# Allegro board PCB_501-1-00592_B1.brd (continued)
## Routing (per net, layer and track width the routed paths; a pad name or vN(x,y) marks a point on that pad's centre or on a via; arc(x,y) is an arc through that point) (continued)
PCIE_NVM_RX2_N: length 48.8
  TOP w0.114: J7.17 20.59,24.72 20.5,24.82 18.06,24.82 17.91,24.67 17.91,24.42 18.02,24.3 19.03,24.3 19.25,24.08 19.25,23.53 18.96,23.23 18.02,23.23 17.91,23.12 17.91,22.89 18.02,22.78 19.03,22.78 19.25,22.55 19.25,22.02 18.95,21.71 18.02,21.71 17.91,21.6 17.91,21.37 18.02,21.25 19.03,21.25 19.25,21.03 19.25,20.48 18.96,20.19 18.02,20.19 17.91,20.07 17.91,19.8 18.02,19.69 19.08,19.69 19.3,19.46 19.3,18.92 19.01,18.62 18.02,18.62 17.91,18.51 17.91,18.28 18.02,18.17 19.08,18.17 19.3,17.94 19.3,17.39 19.01,17.1 18.02,17.1 17.91,16.98 17.91,16.76 18.02,16.64 19.08,16.64 19.3,16.42 19.3,15.87 19.01,15.58 18.02,15.58 17.91,15.46 17.91,15.22 18.02,15.11 19.04,15.11 19.33,14.81 19.33,14.4 18.97,14.04 11.87,14.04 11.05,14.86 11.05,22.91 9.64,24.31 8.81,24.31 R6.1
PCIE_NVM_RX2_P: length 49.4
  TOP w0.114: R1.1 8.77,24.62 9.77,24.62 9.99,24.4 10.16,24.4 10.22,24.46 10.38,24.46 10.55,24.3 10.55,24.14 10.48,24.07 10.48,23.91 10.64,23.75 10.8,23.75 10.87,23.82 11.03,23.82 11.19,23.66 11.19,23.49 11.13,23.43 11.13,23.27 11.35,23.04 11.35,14.99 11.99,14.35 18.85,14.35 19.02,14.52 19.02,14.69 18.91,14.8 17.9,14.8 17.6,15.09 17.6,15.59 17.9,15.88 18.88,15.88 19,15.99 19,16.22 18.88,16.34 17.9,16.34 17.6,16.63 17.6,17.11 17.9,17.4 18.88,17.4 19,17.52 19,17.75 18.88,17.86 17.9,17.86 17.6,18.15 17.6,18.64 17.9,18.93 18.88,18.93 19,19.04 19,19.27 18.88,19.39 17.9,19.39 17.6,19.68 17.6,20.2 17.9,20.49 18.83,20.49 18.95,20.61 18.95,20.83 18.83,20.95 17.9,20.95 17.6,21.24 17.6,21.72 17.9,22.02 18.82,22.02 18.95,22.14 18.95,22.36 18.83,22.47 17.9,22.47 17.6,22.77 17.6,23.25 17.9,23.54 18.83,23.54 18.95,23.65 18.95,23.88 18.83,24 17.9,24 17.6,24.29 17.6,24.79 17.93,25.12 20.37,25.12 20.47,25.22 J7.19
PCIE_NVM_RX3_N: length 44.3
  TOP w0.114: J7.5 21.82,21.72 21.92,21.82 22.81,21.82 23.03,21.6 23.03,21.44 22.9,21.31 22.9,21.15 23.06,20.99 23.22,20.99 23.35,21.12 23.51,21.12 23.83,20.8 23.83,18.27 23.69,18.13 22.31,18.13 22.02,17.83 22.02,17.35 22.31,17.06 23.71,17.06 23.83,16.95 23.83,16.74 23.69,16.6 22.31,16.6 22.02,16.31 22.02,15.83 22.31,15.54 23.71,15.54 23.83,15.42 23.83,15.22 23.69,15.08 22.31,15.08 22.02,14.79 22.02,14.3 22.31,14.01 23.71,14.01 23.83,13.9 23.83,13.41 23.7,13.28 10.79,13.28 9.93,14.15 9.93,21.72 9.35,22.3 8.81,22.3 R8.1
PCIE_NVM_RX3_P: length 44.8
  TOP w0.114: R7.1 8.78,22 9.22,22 9.63,21.59 9.63,14.02 10.67,12.98 23.83,12.98 24.13,13.28 24.13,14.02 23.84,14.32 22.44,14.32 22.33,14.43 22.33,14.66 22.44,14.77 23.81,14.77 24.13,15.09 24.13,15.57 23.86,15.84 22.44,15.84 22.33,15.96 22.33,16.18 22.44,16.3 23.81,16.3 24.13,16.62 24.13,17.1 23.86,17.36 22.44,17.36 22.33,17.48 22.33,17.71 22.44,17.82 23.81,17.82 24.13,18.14 24.13,20.93 22.93,22.12 21.87,22.12 21.77,22.22 J7.7
PCIE_NVM_RX4_N: length 38.8
  TOP w0.114: J8.41 20.51,68.95 20.41,69.05 19.92,69.05 18.72,67.85 18.72,67.69 18.84,67.57 18.84,67.41 18.68,67.25 18.52,67.25 18.4,67.36 18.24,67.36 13.56,62.69 13.56,42.19 10.22,38.84 10.22,38.68 10.3,38.6 10.3,38.44 10.14,38.28 9.98,38.28 9.9,38.36 9.73,38.36 9.39,38.01 8.85,38.01 8.43,37.59 R10.1
PCIE_NVM_RX4_P: length 37.8
  TOP w0.114: R9.1 8.43,38.74 8.85,38.32 9.26,38.32 13.26,42.32 13.26,62.81 19.8,69.35 20.43,69.35 20.53,69.45 J8.43
PCIE_NVM_RX5_N: length 42.8
  TOP w0.114: J8.29 21.02,66.07 18.82,66.07 18.3,65.54 18.3,65.38 18.4,65.27 18.4,65.11 18.24,64.95 18.08,64.95 17.97,65.06 17.81,65.06 17.65,64.89 17.65,64.73 17.75,64.63 17.75,64.47 17.59,64.3 17.43,64.3 17.33,64.41 17.16,64.41 14.63,61.87 14.63,40.39 13.89,39.64 13.47,39.64 12.94,40.18 12.77,40.18 12.61,40.02 12.61,39.86 13.15,39.32 13.15,38.91 12.81,38.57 12.39,38.57 11.86,39.1 11.7,39.1 11.53,38.94 11.53,38.78 12.07,38.24 12.07,37.83 10.03,35.79 8.86,35.79 R12.1
PCIE_NVM_RX5_P: length 41.8
  TOP w0.114: R11.1 8.73,36.09 9.91,36.09 11.77,37.95 11.77,38.11 11.23,38.65 11.23,39.07 11.57,39.41 11.98,39.41 12.52,38.87 12.68,38.87 12.84,39.03 12.84,39.19 12.31,39.73 12.31,40.15 12.65,40.49 13.06,40.49 13.6,39.95 13.76,39.95 14.33,40.51 14.33,62 18.69,66.37 21.04,66.37 21.12,66.45 J8.31
PCIE_NVM_RX6_N: length 46
  TOP w0.114: R14.1 8.79,33.44 9.54,33.44 15.65,39.55 15.65,50.29 15.76,50.41 16.47,50.41 16.76,50.7 16.76,51.18 16.47,51.48 15.76,51.48 15.65,51.59 15.65,51.82 15.76,51.93 16.47,51.93 16.76,52.23 16.76,52.71 16.47,53 15.76,53 15.65,53.11 15.65,53.34 15.76,53.46 16.47,53.46 16.76,53.75 16.76,54.23 16.47,54.52 15.76,54.52 15.65,54.64 15.65,54.87 15.76,54.98 16.47,54.98 16.76,55.27 16.76,55.76 16.47,56.05 15.76,56.05 15.65,56.16 15.65,61.39 17.3,63.04 18.26,63.04 18.38,62.93 18.38,62.8 18.49,62.69 18.72,62.69 18.83,62.8 18.83,62.93 18.95,63.04 19.18,63.04 19.29,62.93 19.29,62.8 19.41,62.69 19.63,62.69 19.75,62.8 19.75,62.93 19.86,63.04 21.05,63.04 J8.17
PCIE_NVM_RX6_P: length 45.1
  TOP w0.114: J8.19 21.04,63.35 17.17,63.35 15.34,61.52 15.34,56.04 15.63,55.74 16.34,55.74 16.46,55.63 16.46,55.4 16.34,55.29 15.63,55.29 15.34,54.99 15.34,54.51 15.63,54.22 16.34,54.22 16.46,54.1 16.46,53.88 16.34,53.76 15.63,53.76 15.34,53.47 15.34,52.99 15.63,52.69 16.34,52.69 16.46,52.58 16.46,52.35 16.34,52.24 15.63,52.24 15.34,51.95 15.34,51.46 15.63,51.17 16.34,51.17 16.46,51.06 16.46,50.83 16.34,50.71 15.63,50.71 15.34,50.42 15.34,39.67 9.41,33.74 8.79,33.74 R13.1
PCIE_NVM_RX7_N: length 48.5
  TOP w0.114: J8.5 20.47,59.95 20.37,60.05 19.43,60.05 18.16,61.32 17.2,61.32 16.59,60.71 16.59,60.08 16.74,59.92 16.74,59.47 16.59,59.31 16.59,58.86 16.74,58.7 16.74,58.25 16.59,58.09 16.59,57.23 17.6,56.21 17.6,49.55 17.31,49.26 16.68,49.26 16.56,49.15 16.56,48.92 16.68,48.8 17.31,48.8 17.6,48.51 17.6,48.03 17.31,47.74 16.68,47.74 16.56,47.62 16.56,47.39 16.68,47.28 17.31,47.28 17.6,46.99 17.6,46.51 17.31,46.21 16.68,46.21 16.56,46.1 16.56,45.87 16.68,45.76 17.31,45.76 17.6,45.46 17.6,44.98 17.31,44.69 16.68,44.69 16.56,44.57 16.56,44.35 16.68,44.23 17.31,44.23 17.6,43.94 17.6,43.46 17.31,43.17 16.68,43.17 16.56,43.05 16.56,42.82 16.68,42.71 17.31,42.71 17.6,42.42 17.6,38.91 9.84,31.15 8.79,31.15 R16.1
PCIE_NVM_RX7_P: length 48.2
  TOP w0.114: R15.1 8.41,31.88 8.83,31.46 9.72,31.46 17.3,39.04 17.3,42.29 17.18,42.4 16.55,42.4 16.26,42.7 16.26,43.18 16.55,43.47 17.18,43.47 17.3,43.58 17.3,43.81 17.18,43.93 16.55,43.93 16.26,44.22 16.26,44.7 16.55,44.99 17.18,44.99 17.3,45.11 17.3,45.34 17.18,45.45 16.55,45.45 16.26,45.74 16.26,46.23 16.55,46.52 17.18,46.52 17.3,46.63 17.3,46.86 17.18,46.98 16.55,46.98 16.26,47.27 16.26,47.75 16.55,48.04 17.18,48.04 17.3,48.16 17.3,48.38 17.18,48.5 16.55,48.5 16.26,48.79 16.26,49.27 16.55,49.57 17.18,49.57 17.3,49.68 17.3,56.08 16.28,57.1 16.28,60.83 17.07,61.62 18.29,61.62 19.56,60.35 20.37,60.35 20.47,60.45 J8.7
PCIE_NVM_TX0_N: length 50.1
  TOP w0.114: v2(22.26,32.21) 22.15,32.32 21.83,32.32 21.73,32.22 J7.47
  BOTTOM w0.114: v2(22.26,32.21) 22.39,32.33 23.88,32.33 24.21,32 24.21,31.7 24.09,31.59 23.94,31.59 23.83,31.47 23.83,31.25 23.94,31.13 24.07,31.13 24.21,30.99 24.21,30.79 24.09,30.67 23.94,30.67 23.83,30.56 23.83,30.33 23.94,30.22 24.07,30.22 24.21,30.08 24.21,8.59 23.67,8.05 17.91,8.05 17.32,8.64 17.32,21.89 16.9,22.31 16.28,22.31 R79.2
PCIE_NVM_TX0_P: length 50.2
  TOP w0.114: J7.49 21.76,32.72 21.86,32.62 22.15,32.62 v2(22.26,32.74)
  BOTTOM w0.114: v2(22.26,32.74) 22.36,32.64 24,32.64 24.51,32.13 24.51,8.46 23.8,7.75 17.78,7.75 17.02,8.51 17.02,21.77 16.78,22.01 16.29,22.01 R78.2
PCIE_NVM_TX1_N: length 53.4
  TOP w0.114: J7.35 21.75,29.22 21.85,29.32 22.61,29.32 v2(22.72,29.21)
  BOTTOM w0.114: v2(22.72,29.21) 22.83,29.31 23.09,29.31 23.32,29.08 23.32,18.43 23.2,18.32 23.05,18.32 22.94,18.2 22.94,17.98 23.05,17.86 23.2,17.86 23.32,17.75 23.32,17.52 23.2,17.4 23.05,17.4 22.94,17.29 22.94,17.06 23.05,16.95 23.2,16.95 23.32,16.83 23.32,15.39 23.2,15.28 22.72,15.28 22.43,14.98 22.43,14.5 22.72,14.21 23.2,14.21 23.32,14.1 23.32,13.87 23.2,13.75 22.72,13.75 22.43,13.46 22.43,12.98 22.72,12.69 23.2,12.69 23.32,12.57 23.32,12.34 23.2,12.23 22.72,12.23 22.43,11.94 22.43,11.46 22.72,11.16 23.2,11.16 23.32,11.05 23.32,10.82 23.2,10.71 22.72,10.71 22.43,10.41 22.43,9.93 22.72,9.64 23.18,9.64 23.32,9.5 23.32,9.3 23.17,9.14 18.67,9.14 18.49,9.32 18.49,22.91 17.56,23.84 12.98,23.84 R81.2
PCIE_NVM_TX1_P: length 53.4
  TOP w0.114: J7.37 21.76,29.72 21.86,29.62 22.61,29.62 v2(22.72,29.74)
  BOTTOM w0.114: R80.2 12.98,23.53 17.44,23.53 18.19,22.78 18.19,9.19 18.54,8.84 23.29,8.84 23.62,9.17 23.62,9.63 23.3,9.94 22.85,9.94 22.73,10.06 22.73,10.29 22.85,10.4 23.33,10.4 23.62,10.69 23.62,11.17 23.33,11.47 22.85,11.47 22.73,11.58 22.73,11.81 22.85,11.92 23.33,11.92 23.62,12.22 23.62,12.7 23.33,12.99 22.85,12.99 22.73,13.11 22.73,13.33 22.85,13.45 23.33,13.45 23.62,13.74 23.62,14.22 23.33,14.52 22.85,14.52 22.73,14.63 22.73,14.86 22.85,14.97 23.33,14.97 23.62,15.27 23.62,29.21 23.22,29.62 22.84,29.62 v2(22.72,29.74)
PCIE_NVM_TX2_N: length 50.1
  TOP w0.114: v2(16.6,25.36) 16.6,25.21 16.41,25.02 16.41,24.77 16.29,24.65 16.09,24.65 15.98,24.54 15.98,24.31 16.09,24.2 16.29,24.2 16.41,24.08 16.41,23.24 16.29,23.13 14.95,23.13 14.66,22.83 14.66,22.35 14.95,22.06 16.29,22.06 16.41,21.95 16.41,21.72 16.29,21.6 14.95,21.6 14.66,21.31 14.66,20.83 14.95,20.54 16.29,20.54 16.41,20.42 16.41,20.19 16.29,20.08 14.95,20.08 14.66,19.79 14.66,19.3 14.95,19.01 16.29,19.01 16.41,18.9 16.41,18.67 16.29,18.55 14.95,18.55 14.66,18.26 14.66,17.78 14.95,17.49 16.29,17.49 16.41,17.37 16.41,17.14 16.29,17.03 14.95,17.03 14.66,16.74 14.66,16.26 14.95,15.96 16.29,15.96 16.41,15.85 16.41,15.52 16.23,15.34 13.31,15.34 12.57,16.08 12.57,25.25 13.64,26.32 17.53,26.32 17.65,26.21 17.65,26.02 17.76,25.91 17.99,25.91 18.1,26.02 18.1,26.21 18.22,26.32 18.45,26.32 18.56,26.21 18.56,26.02 18.67,25.91 18.9,25.91 19.02,26.02 19.02,26.21 19.13,26.32 20.39,26.32 20.49,26.22 J7.23
  BOTTOM w0.114: v2(16.6,25.36) 16.28,25.36 R83.2
PCIE_NVM_TX2_P: length 50.2
  TOP w0.114: J7.25 20.55,26.72 20.45,26.62 13.52,26.62 12.27,25.37 12.27,15.95 13.18,15.04 16.36,15.04 16.71,15.39 16.71,15.98 16.42,16.27 15.07,16.27 14.96,16.38 14.96,16.61 15.07,16.73 16.42,16.73 16.71,17.02 16.71,17.5 16.42,17.79 15.07,17.79 14.96,17.91 14.96,18.14 15.07,18.25 16.42,18.25 16.71,18.54 16.71,19.02 16.42,19.32 15.07,19.32 14.96,19.43 14.96,19.66 15.07,19.77 16.42,19.77 16.71,20.07 16.71,20.55 16.42,20.84 15.07,20.84 14.96,20.95 14.96,21.18 15.07,21.3 16.42,21.3 16.71,21.59 16.71,22.07 16.42,22.36 15.07,22.36 14.96,22.48 14.96,22.71 15.07,22.82 16.42,22.82 16.71,23.11 16.71,24.89 16.88,25.06 v2(17.04,25.06)
  BOTTOM w0.114: R82.2 16.18,24.95 16.94,24.95 v2(17.04,25.06)
PCIE_NVM_TX3_N: length 53.5
  TOP w0.114: J7.11 21.05,23.32 20.15,23.32 v2(20.04,23.21)
  BOTTOM w0.114: R85.2 12.98,26.89 20.92,26.89 21.39,26.42 21.39,25.07 21.01,24.69 19.68,24.69 19.33,24.33 19.33,17.79 19.47,17.65 20.05,17.65 20.35,17.35 20.35,16.87 20.05,16.58 19.44,16.58 19.33,16.47 19.33,16.26 19.47,16.12 20.05,16.12 20.35,15.83 20.35,15.35 20.05,15.06 19.44,15.06 19.33,14.94 19.33,14.74 19.47,14.6 20.05,14.6 20.35,14.31 20.35,13.82 20.05,13.53 19.44,13.53 19.33,13.42 19.33,13.21 19.47,13.08 20.05,13.08 20.35,12.78 20.35,12.3 20.05,12.01 19.44,12.01 19.33,11.89 19.33,11.69 19.47,11.55 20.05,11.55 20.35,11.26 20.35,10.78 20.05,10.48 19.42,10.48 19.3,10.37 19.3,10.13 19.46,9.98 21.18,9.98 21.39,10.19 21.39,20.62 21.27,20.73 21.09,20.73 20.98,20.84 20.98,21.07 21.09,21.19 21.27,21.19 21.39,21.3 21.39,21.53 21.27,21.64 21.09,21.64 20.98,21.76 20.98,21.99 21.09,22.1 21.27,22.1 21.39,22.22 21.39,22.66 20.73,23.32 20.15,23.32 v2(20.04,23.21)
PCIE_NVM_TX3_P: length 53.4
  TOP w0.114: v2(20.04,23.74) 20.15,23.62 21.04,23.62 J7.13
  BOTTOM w0.114: R84.2 12.98,26.58 20.79,26.58 21.08,26.29 21.08,25.2 20.88,24.99 19.56,24.99 19.02,24.46 19.02,17.66 19.34,17.34 19.93,17.34 20.04,17.23 20.04,17 19.93,16.89 19.32,16.89 19.02,16.59 19.02,16.14 19.34,15.82 19.93,15.82 20.04,15.7 20.04,15.48 19.93,15.36 19.32,15.36 19.02,15.07 19.02,14.61 19.34,14.29 19.93,14.29 20.04,14.18 20.04,13.95 19.93,13.84 19.32,13.84 19.02,13.54 19.02,13.09 19.34,12.77 19.93,12.77 20.04,12.66 20.04,12.43 19.93,12.31 19.32,12.31 19.02,12.02 19.02,11.56 19.34,11.25 19.93,11.25 20.04,11.13 20.04,10.9 19.93,10.79 19.29,10.79 19,10.5 19,10.01 19.33,9.68 21.31,9.68 21.69,10.06 21.69,22.78 20.85,23.62 20.15,23.62 v2(20.04,23.74)
PCIE_NVM_TX4_N: length 50.6
  TOP w0.114: v2(20.04,70.43) 20.09,70.43 20.21,70.55 20.4,70.55 20.51,70.45 J8.47
  BOTTOM w0.114: v2(20.04,70.43) 20.09,70.43 20.19,70.54 22.5,70.54 23.24,69.8 23.24,69.5 23.13,69.38 23.03,69.38 22.91,69.27 22.91,69.04 23.03,68.93 23.13,68.93 23.24,68.81 23.24,68.13 23.13,68.02 22.97,68.02 22.86,67.9 22.86,67.67 22.97,67.56 23.13,67.56 23.24,67.44 23.24,51.84 19,47.6 19,30.96 16.45,28.41 16.29,28.41 R87.2
PCIE_NVM_TX4_P: length 50.7
  TOP w0.114: v2(20.04,70.97) 20.09,70.97 20.2,70.86 20.39,70.86 20.48,70.95 J8.49
  BOTTOM w0.114: R86.2 16.29,28.11 16.57,28.11 19.3,30.84 19.3,47.47 23.55,51.71 23.55,69.93 22.63,70.84 20.22,70.84 20.09,70.97 v2(20.04,70.97)
PCIE_NVM_TX5_N: length 53.4
  TOP w0.114: J8.35 20.46,67.45 20.36,67.55 19.79,67.55 v2(19.67,67.43)
  BOTTOM w0.114: v2(19.67,67.43) 19.8,67.56 20.63,67.56 21.54,66.65 21.54,57.79 21.42,57.68 21.3,57.68 21.18,57.56 21.18,57.33 21.3,57.22 21.42,57.22 21.54,57.1 21.54,56.87 21.42,56.76 21.3,56.76 21.18,56.65 21.18,56.42 21.3,56.3 21.42,56.3 21.54,56.19 21.54,55.73 21.24,55.42 20.23,55.42 19.94,55.13 19.94,54.65 20.23,54.36 21.37,54.36 21.49,54.24 21.49,54.04 21.35,53.9 20.23,53.9 19.94,53.61 19.94,53.13 20.23,52.83 21.37,52.83 21.49,52.72 21.49,52.46 21.35,52.32 20.37,52.32 19.74,51.69 19.74,50.19 17.83,48.29 17.83,31.17 16.6,29.93 12.98,29.93 R89.2
PCIE_NVM_TX5_P: length 53.5
  TOP w0.114: v2(19.67,67.97) 19.79,67.85 20.38,67.85 20.47,67.95 J8.37
  BOTTOM w0.114: v2(19.67,67.97) 19.77,67.87 20.75,67.87 21.84,66.78 21.84,55.6 21.36,55.12 20.36,55.12 20.24,55 20.24,54.78 20.36,54.66 21.5,54.66 21.79,54.37 21.79,53.91 21.48,53.6 20.36,53.6 20.24,53.48 20.24,53.28 20.36,53.16 21.5,53.16 21.79,52.87 21.79,52.34 21.48,52.02 20.5,52.02 20.04,51.56 20.04,50.06 18.14,48.16 18.14,31.04 16.73,29.63 12.98,29.63 R88.2
PCIE_NVM_TX6_N: length 50.1
  TOP w0.114: J8.23 20.49,64.45 20.39,64.55 20.1,64.55 v2(19.99,64.43)
  BOTTOM w0.114: R91.2 16.29,31.46 16.65,31.46 16.87,31.67 16.87,50.53 17.16,50.82 18.3,50.82 18.41,50.94 18.41,51.17 18.3,51.28 17.16,51.28 16.87,51.57 16.87,52.06 17.16,52.35 18.3,52.35 18.41,52.46 18.41,52.69 18.3,52.81 17.16,52.81 16.87,53.1 16.87,53.58 17.16,53.87 18.3,53.87 18.41,53.99 18.41,54.21 18.3,54.33 17.16,54.33 16.87,54.62 16.87,55.1 17.16,55.4 18.3,55.4 18.41,55.51 18.41,55.74 18.3,55.85 17.16,55.85 16.87,56.15 16.87,56.76 17.16,57.05 19.1,57.05 20.7,58.65 20.7,62.33 20.59,62.45 20.46,62.45 20.35,62.56 20.35,62.79 20.46,62.9 20.59,62.9 20.7,63.02 20.7,63.25 20.59,63.36 20.46,63.36 20.35,63.48 20.35,63.7 20.46,63.82 20.59,63.82 20.7,63.93 20.7,64.34 20.47,64.57 20.12,64.57 v2(19.99,64.43)
PCIE_NVM_TX6_P: length 50.2
  TOP w0.114: v2(19.99,64.97) 20.1,64.85 20.37,64.85 20.47,64.95 J8.25
  BOTTOM w0.114: v2(19.99,64.97) 20.08,64.87 20.6,64.87 21.01,64.46 21.01,58.52 19.23,56.74 17.28,56.74 17.17,56.63 17.17,56.27 17.28,56.16 18.43,56.16 18.72,55.87 18.72,55.38 18.43,55.09 17.28,55.09 17.17,54.98 17.17,54.75 17.28,54.63 18.43,54.63 18.72,54.34 18.72,53.86 18.43,53.57 17.28,53.57 17.17,53.45 17.17,53.22 17.28,53.11 18.43,53.11 18.72,52.82 18.72,52.34 18.43,52.04 17.28,52.04 17.17,51.93 17.17,51.7 17.28,51.59 18.43,51.59 18.72,51.29 18.72,50.81 18.43,50.52 17.28,50.52 17.17,50.4 17.17,31.55 16.78,31.15 16.29,31.15 R90.2
PCIE_NVM_TX7_N: length 53.5
  TOP w0.114: J8.13 20.47,61.95 20.37,61.85 20.1,61.85 v2(19.99,61.97)
  BOTTOM w0.114: R93.2 12.98,32.85 13.78,32.85 15.82,34.9 15.82,48.7 15.71,48.81 14.34,48.81 14.05,49.1 14.05,49.58 14.34,49.88 15.66,49.88 15.82,50.04 15.82,50.22 15.71,50.33 14.34,50.33 14.05,50.63 14.05,51.11 14.34,51.4 15.66,51.4 15.82,51.57 15.82,51.74 15.71,51.86 14.34,51.86 14.05,52.15 14.05,52.63 14.34,52.92 15.66,52.92 15.82,53.09 15.82,53.27 15.71,53.38 14.34,53.38 14.05,53.67 14.05,54.16 14.34,54.45 15.66,54.45 15.82,54.61 15.82,54.79 15.71,54.91 14.34,54.91 14.05,55.2 14.05,55.68 14.34,55.97 15.66,55.97 15.82,56.14 15.82,56.55 15.71,56.67 14.4,56.67 14.11,56.96 14.11,57.57 14.4,57.86 16.64,57.86 18.69,59.92 18.69,61.46 19.06,61.83 19.85,61.83 v2(19.99,61.97)
PCIE_NVM_TX7_P: length 53.6
  TOP w0.114: J8.11 20.49,61.45 20.39,61.55 20.1,61.55 v2(19.99,61.43)
  BOTTOM w0.114: R92.2 12.98,32.55 13.91,32.55 16.13,34.77 16.13,48.82 15.84,49.11 14.47,49.11 14.35,49.23 14.35,49.46 14.47,49.57 15.79,49.57 16.13,49.92 16.13,50.4 15.89,50.64 14.47,50.64 14.35,50.75 14.35,50.98 14.47,51.1 15.79,51.1 16.13,51.44 16.13,51.92 15.89,52.16 14.47,52.16 14.35,52.28 14.35,52.51 14.47,52.62 15.79,52.62 16.13,52.96 16.13,53.44 15.89,53.69 14.47,53.69 14.35,53.8 14.35,54.03 14.47,54.14 15.79,54.14 16.13,54.49 16.13,54.97 15.89,55.21 14.47,55.21 14.35,55.33 14.35,55.55 14.47,55.67 15.79,55.67 16.13,56.01 16.13,56.69 15.85,56.97 14.53,56.97 14.41,57.09 14.41,57.44 14.53,57.56 16.76,57.56 19,59.79 19,61.34 19.18,61.52 19.9,61.52 v2(19.99,61.43)
PERST1#: length 19.3
  TOP w0.152: J7.50 29.79,32.97 v2(29.79,32.97)
  BOTTOM w0.152: R32.1 30.73,33.91 v2(29.79,32.97) ; R32.1 R25.2 ; R32.1 31.28,33.38 40.48,33.38 R119.2
PERST2#: length 6.5
  TOP w0.152: J8.50 v2(29.67,71.2)
  BOTTOM w0.152: 30.33,71.2 30.74,70.78 R48.1 ; 30.33,71.2 30.74,71.61 R26.2 31.28,72.16 33.89,72.16 R120.2 ; 30.33,71.2 v2(29.67,71.2)
PGOOD_3V3_A: length 108.6
  TOP w0.152: v2(123.52,19.68) v2(128.02,19.68)
  BOTTOM w0.152: M1.8 v2(123.52,19.68) ; R67.1 43.56,38.47 R119.1 R66.1 47.76,40.51 121.16,40.51 129.49,32.18 129.49,21.16 v2(128.02,19.68)
PGOOD_3V3_B: length 123.7
  TOP w0.152: v2(131.44,86.87) v2(126.8,86.87)
  BOTTOM w0.152: M2.8 v2(126.8,86.87) ; v2(131.44,86.87) 133.98,86.87 135.13,85.72 135.13,74.68 130.3,69.85 108.97,69.85 106.67,72.14 R114.1 R118.1 35.93,72.14 R120.1
PWR_RST#_COMM: length 48.6
  BOTTOM w0.152: R26.1 32,71.37 R76.1 34.58,71.37 35.31,70.64 Q4.3 36.64,70.44 38.1,68.99 38.1,64.14 R77.2 39.12,61.84 39.12,37.08 37.08,35.05 R25.1
SS/TR_3V3_A: length 1.8
  BOTTOM w0.152: M1.28 120.32,9.06 C39.2
SS/TR_3V3_B: length 1.8
  BOTTOM w0.152: C58.2 123.6,76.24 M2.28
STSEL_3V3_A: length 1.9
  BOTTOM w0.152: M1.29 119.52,9.4 R63.2
STSEL_3V3_B: length 1.9
  BOTTOM w0.152: R112.2 122.8,76.59 M2.29
UVLO_1: length 3.2
  BOTTOM w0.152: R107.1 R106.2 118.72,9.75 M1.30
UVLO_2: length 3.2
  BOTTOM w0.152: M2.30 122,76.93 R111.2 R109.1
VADJ_3V3_A: length 1.9
  BOTTOM w0.152: R64.1 121.92,9.38 M1.26
VADJ_3V3_B: length 1.9
  BOTTOM w0.152: R110.1 125.2,76.57 M2.26
N2986241: length 2.6
  BOTTOM w0.152: R19.1 R17.1 2.1,33.96 J1.34
N16765591: length 1.4
  TOP w0.381: D4.1 144.19,28.86 R60.1
N16765603:
  vias: v1(145.11,34.19) v1(145.62,30.51) v1(145.87,35.33) v1(145.87,32.54) v1(146,37.87) v1(147.02,31.14) v1(147.27,36.6) v1(147.27,34.19) v1(148.92,37.87) v1(148.92,32.66) v1(148.92,31.14) v1(150.19,36.6) v1(150.32,34.32) v1(150.44,31.14) v1(151.97,37.87) v1(152.22,32.66) v1(152.4,40.54) v1(152.35,31.14) v1(153.37,41.3) v1(153.37,39.78) v1(153.37,36.6) v1(153.49,34.32) v1(154.25,30.89) v1(155.4,39.27) v1(155.4,37.87) v1(155.4,35.59) v1(155.4,32.28) v1(155.52,30) v1(156.67,38.63) v1(156.67,34.82) v1(156.67,33.17) v1(157.43,41.38) v1(157.43,40.03) v1(158.19,38.63) v1(158.19,34.82) v1(158.19,33.17) v1(158.57,40.67)
N19373667: length 3.3
  BOTTOM w0.152: J1.33 11.1,33.96 R18.1 R20.1
N19381543: length 2.9
  TOP w0.152: v2(27.43,33.4) 27.5,33.47 J7.52
  BOTTOM w0.152: v2(27.43,33.4) R36.2 R33.1
N19381958: length 3.6
  TOP w0.152: v2(30.1,72.14) 29.66,71.7 J8.52
  BOTTOM w0.152: R52.2 R49.1 30.11,72.14 v2(30.1,72.14)
N19382544: length 3.3
  TOP w0.152: v2(30.1,31.62) 29.95,31.47 J7.44
  BOTTOM w0.152: v2(30.1,31.62) R31.1 R34.2
N19383230: length 3
  TOP w0.152: J8.44 v2(27.46,69.7)
  BOTTOM w0.152: R47.1 R50.2 27.07,69.7 v2(27.46,69.7)
N19387719: length 3.7
  BOTTOM w0.152: R41.1 R42.2 R68.1 37.08,40.01 Y3.1
N19387935: length 3.9
  BOTTOM w0.152: Y4.1 37.33,78.23 R69.1 R58.2 R57.1
N19416578: length 2.3
  TOP w0.152: v2(30.23,29.34) 29.59,29.97 J7.38
  BOTTOM w0.152: R70.2 v2(30.23,29.34)
N19421657: length 2.1
  TOP w0.152: J8.38 v2(29.84,68.2)
  BOTTOM w0.152: v2(29.84,68.2) R71.2
N19429194: length 2.1
  TOP w0.152: J7.68 v2(30.23,37.47)
  BOTTOM w0.152: R72.2 30.23,37.47 v2(30.23,37.47)
N19429230: length 2.1
  TOP w0.152: J8.68 v2(29.96,75.7)
  BOTTOM w0.152: R73.2 30.73,75.7 v2(29.96,75.7)
N19444474: length 3.4
  BOTTOM w0.152: Q3.3 35.77,66.12 R75.1 36.33,68.17 Q4.1
N19453893: length 3.2
  BOTTOM w0.254: Q6.3 33.66,19.18 R95.1 33.66,17.64 Q5.1
N19454725: length 1.2
  TOP w0.254: D5.1 R94.1
N19454731: length 2.9
  TOP w0.254: D5.2 31.41,13.72 v2(31.41,15.28)
  BOTTOM w0.254: Q5.3 v2(31.41,15.28)
N19455675: length 1.2
  TOP w0.254: D7.1 R100.1
N19455677: length 3.3
  BOTTOM w0.254: Q7.1 33.28,55.74 R101.1 33.27,57.54 Q8.3
N19455687: length 2.9
  TOP w0.254: D7.2 v2(31.02,53.47)
  BOTTOM w0.254: Q7.3 31.03,53.47 v2(31.02,53.47)
N19467364: length 3.6
  BOTTOM w0.381: v2(125.49,16.97) 125.49,17.63 125.12,18.01 M1.10
  vias: v2(120.34,16.13) v2(120.34,14.86) v2(121.53,16.13) v2(121.56,15.49) v2(121.56,14.86) v2(122.6,16.15) v2(122.6,14.86) v2(123.08,15.47) v2(123.72,14.86) v2(123.74,16.13) v2(124.58,16.92) v2(124.55,16.26) v2(124.61,15.49) v2(124.58,14.73) v2(124.58,14.07) v2(125.47,16.31) v2(125.47,15.52) v2(125.47,14.78) v2(125.47,14.07)
N19467701: length 1.6
  BOTTOM w0.152: R105.2 125.12,9.24 M1.22
N19470945: length 2.6
  TOP w0.152: R108.1 119.88,19.41 v2(119.91,19.43)
  BOTTOM w0.152: v2(119.91,19.43) 120.32,19.85 M1.4
N19472498: length 3.6
  BOTTOM w0.381: v2(128.78,84.15) 128.78,84.96 128.4,85.34 M2.10
  vias: v2(123.62,83.31) v2(123.62,82.04) v2(124.82,83.31) v2(124.84,82.68) v2(124.84,82.04) v2(125.88,83.34) v2(125.88,82.04) v2(126.37,82.65) v2(127,82.04) v2(127.03,83.31) v2(127.86,84.1) v2(127.84,83.44) v2(127.89,82.68) v2(127.86,81.91) v2(127.86,81.25) v2(128.75,83.49) v2(128.75,82.7) v2(128.75,81.97) v2(128.75,81.25)
N19472885: length 1.8
  TOP w0.152: v2(123.19,86.61) 123.19,85.99 R113.1
  BOTTOM w0.152: M2.4 123.6,87.03 v2(123.19,86.61)
N19472919: length 1.6
  BOTTOM w0.152: R115.2 128.4,76.42 M2.22
N19474380: length 98.7
  TOP w0.152: v2(42.55,39.24) 42.55,80.26 37.08,85.72 8.64,85.72 1.79,78.88 v2(1.79,69.46)
  BOTTOM w0.152: R67.2 v2(42.55,39.24) ; J1.102 v2(1.79,69.46)
N19474383: length 42.7
  TOP w0.152: v2(4.42,69.96) 4.45,69.98 5.58,69.98 6.09,70.48 6.09,73.14 14.48,81.53 28.19,81.53 v2(35.94,73.78)
  BOTTOM w0.152: J1.104 v2(4.42,69.96) ; v2(35.94,73.78) R118.2
N19528011:
  vias: v1(153.37,46.76) v1(153.37,45.62) v1(153.37,44.22) v1(153.49,43.08) v1(157.18,43.21) v1(157.43,46.96) v1(157.43,45.75) v1(157.43,44.35)

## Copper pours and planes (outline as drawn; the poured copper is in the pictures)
GND_POWER on TOP (solid shape): 128.78,79.76 131.19,79.76 131.44,79.5 131.44,76.71 131.06,76.33 129.41,76.33 128.91,76.83 128.91,78.36 128.65,78.61 122.05,78.61 121.67,78.23 121.67,77.34 121.54,77.22 119.76,77.22 119.63,77.34 119.63,80.11 119.92,80.39 122.46,80.39 122.59,80.52 128.02,80.52
GND_POWER on TOP (solid shape): 125.49,12.57 127.91,12.57 128.16,12.32 128.16,11.28 128.15,11.28 128.15,10.83 128.16,10.83 128.16,9.53 127.78,9.14 126.13,9.14 125.62,9.65 125.62,11.18 125.37,11.43 118.76,11.43 118.38,11.05 118.38,10.16 118.26,10.03 116.48,10.03 116.35,10.16 116.35,12.92 116.64,13.21 119.18,13.21 119.3,13.33 124.73,13.33
GND_POWER on BOTTOM (solid shape): 123.52,80.39 128.14,80.39 128.78,79.76 129.13,79.76 129.26,79.63 131.19,79.63 131.19,76.83 130.68,76.33 129.41,76.33 128.91,76.83 128.91,78.36 128.65,78.61 128.4,78.61 128.4,78.61 126.87,78.61 126.87,78.61 122.05,78.61 121.87,78.44 121.75,78.44 121.61,78.38 121.55,78.23 121.55,77.22 119.76,77.22 119.63,77.34 119.63,80.11 119.92,80.39 122.46,80.39 122.59,80.52 123.39,80.52
GND_POWER on BOTTOM (solid shape): 120.24,13.21 124.86,13.21 125.49,12.57 125.84,12.57 125.97,12.45 127.91,12.45 127.91,9.65 127.4,9.14 126.13,9.14 125.62,9.65 125.62,11.18 125.37,11.43 125.11,11.43 123.59,11.43 118.76,11.43 118.59,11.26 118.47,11.26 118.32,11.2 118.26,11.05 118.26,10.09 118.26,10.03 116.48,10.03 116.35,10.16 116.35,12.92 116.64,13.21 119.18,13.21 119.3,13.33 120.11,13.33
GND_POWER on TOP: 109.22,3.17 104.9,3.17 103,5.08 103,8.72 103,8.72 103,34.29 107.44,38.74 120.27,38.74 121.03,37.97 121.03,33.66 120.27,32.89 113.54,32.89 112.27,31.62 112.27,8.76 109.47,5.97 109.47,3.43
GND_POWER on TOP: 143.33,54.89 143.33,58.7 142.95,59.08 140.67,59.08 140.28,58.7 140.28,54.89 140.54,54.64 143.08,54.64
GND_POWER on TOP, BOTTOM: 112.65,92.33 114.81,92.33 115.32,91.82 115.32,75.44 113.03,75.44 112.9,75.56 112.9,77.6 112.52,77.98 109.09,77.98 107.44,79.63 107.44,89.79 108.46,90.8 111.12,90.8
GND_POWER on TOP, BOTTOM: 146.38,27.46 152.6,27.46 152.86,27.2 152.86,25.81 152.6,25.55 146.25,25.55 145.87,25.93 145.87,26.95
GND_POWER on TOP, BOTTOM: 162.28,39.12 161.44,38.28 161.44,24.1 162.18,23.37 165,23.37 165.63,24 165.63,38.48 165,39.12
GND_POWER on BOTTOM: 25.02,25.7 25.25,25.93 25.81,25.93 26.05,25.69 26.05,20.97 25.93,20.85 25.22,20.85 25.02,21.06
GND_POWER on BOTTOM: 24.38,59.31 24.38,63.63 24.51,63.75 25.65,63.75 25.78,63.63 25.78,59.44 25.4,59.05 24.64,59.05
GND_POWER on BOTTOM: 36.07,84.33 36.07,81.66 35.43,81.03 34.54,81.03 34.42,80.9 34.42,80.14 34.54,80.01 37.97,80.01 38.35,80.39 38.35,84.33 38.1,84.58 36.32,84.58
GND_POWER on BOTTOM: 30.86,42.93 30.99,42.8 31.75,42.8 31.88,42.67 31.88,41.91 31.75,41.78 29.08,41.78 28.7,42.16 28.7,46.1 28.96,46.36 30.48,46.36 30.86,45.97
GND_POWER on BOTTOM: 109.22,3.17 104.9,3.17 103,5.08 103,34.29 107.44,38.74 120.27,38.74 121.03,37.97 121.03,33.66 120.27,32.89 113.54,32.89 112.27,31.62 112.27,8.76 109.47,5.97 109.47,3.43
GND_POWER on GROUND: 2.44,0.51 166.5,0.51 167.51,1.52 167.51,97.21 166.83,97.89 2.16,97.89 0.33,96.06 0.33,2.62
GND_POWER on POWER: 24.64,73.69 24.64,38.3 25.27,37.67 25.27,35.1 24.64,34.47 24.64,2.03 0.71,2.03 0.71,74.3 24.03,74.3
GND_POWER_AUX on TOP, GROUND: 144.09,72.16 144.09,55.91 144.73,55.27 149.3,55.27 149.81,55.78 149.81,72.16 148.92,73.05 144.98,73.05
SGND1 on TOP (solid shape): outline of 113 points within 117.37,5.59 130.7,21.21
SGND1 on BOTTOM (solid shape): 124.66,10.09 124.68,10 124.73,9.93 124.73,9.24 124.7,9.24 124.7,8.79 124.73,8.79 124.73,5.84 124.48,5.59 117.75,5.59 117.37,5.97 117.37,8.13 117.49,8.26 117.64,8.26 117.64,8.24 118.08,8.24 118.08,8.26 118.78,8.26 118.78,8.24 119.23,8.24 119.23,8.26 119.92,8.26 119.92,8.24 120.37,8.24 120.37,8.26 120.78,8.26 120.78,8.19 120.78,7.58 120.79,7.51 120.82,7.45 121.29,6.73 121.75,7.45 121.78,7.51 121.79,7.58 121.79,8.19 121.79,8.26 122.95,8.26 123.97,9.27 123.97,10.03 123.98,10.09 123.98,11.05 124.66,11.05
SGND2 on TOP (solid shape): outline of 103 points within 120.65,72.77 133.98,88.39
SGND2 on BOTTOM (solid shape): 127.95,77.27 127.96,77.19 128.02,77.12 128.02,76.42 127.99,76.42 127.99,75.97 128.02,75.97 128.02,73.02 127.76,72.77 121.03,72.77 120.65,73.15 120.65,75.31 120.78,75.44 120.92,75.44 120.92,75.42 121.37,75.42 121.37,75.44 124.06,75.44 124.06,75.37 124.06,74.76 124.07,74.69 124.11,74.63 124.57,73.91 125.03,74.63 125.07,74.69 125.08,74.76 125.08,75.37 125.08,75.44 125.48,75.44 125.48,75.43 125.92,75.43 125.92,75.44 126.24,75.44 127.25,76.45 127.25,77.21 127.26,77.27 127.26,78.23 127.95,78.23
VCC_3V3_A on TOP (solid shape): 119.14,17.14 119.14,13.72 119.02,13.59 116.48,13.59 115.97,13.08 115.97,3.83 115.7,3.56 112.27,3.56 112.01,3.81 112.01,7.62 112.27,7.87 112.29,7.87 112.79,8.38 112.79,17.02 113.05,17.27 119.02,17.27
VCC_3V3_A on BOTTOM (solid shape): 119.14,17.14 119.14,13.72 119.02,13.59 116.48,13.59 116.41,13.53 116.37,13.49 116.33,13.45 115.97,13.08 115.97,7.11 115.96,7.1 115.96,3.82 115.7,3.56 112.27,3.56 112.01,3.81 112.01,7.62 112.14,7.75 112.16,7.75 112.79,8.38 112.79,17.02 113.05,17.27 119.02,17.27
VCC_3V3_A on TOP: 29.46,39.37 27.05,39.37 26.8,39.12 26.8,37.97 27.18,37.59 27.69,37.59 27.94,37.85 29.59,37.85 29.72,37.97 29.72,39.12
VCC_3V3_A on TOP: 29.08,25.65 26.67,25.65 26.42,25.4 26.42,21.08 26.8,20.7 29.46,20.7 29.59,20.83 29.59,25.15
VCC_3V3_A on BOTTOM: 26.42,21.08 26.42,25.4 26.67,25.65 27.43,25.65 27.69,25.4 27.69,20.95 27.43,20.7 26.8,20.7
VCC_3V3_A on BOTTOM: 32.64,39.12 32.13,39.62 32.13,46.23 32.64,46.74 34.16,46.74 34.67,46.23 34.67,39.75 34.04,39.12
VCC_3V3_A on BOTTOM: 25.53,38.99 25.53,37.47 25.65,37.34 28.45,37.34 28.57,37.47 28.57,39.24 28.45,39.37 25.91,39.37
VCC_3V3_A on POWER: 25.02,2.03 25.02,48.64 112.52,48.64 112.52,19.68 113.92,18.29 114.68,18.29 116.21,16.76 116.21,2.03
VCC_3V3_B on TOP (solid shape): 122.43,84.33 122.43,80.9 122.3,80.77 119.76,80.77 119.25,80.26 119.25,74.3 116.33,71.37 108.33,71.37 107.95,71.75 107.95,75.06 108.2,75.31 112.14,75.31 112.4,75.06 115.57,75.06 116.08,75.56 116.08,84.2 116.33,84.45 122.3,84.45
VCC_3V3_B on BOTTOM (solid shape): 122.43,84.33 122.43,80.9 122.3,80.77 119.76,80.77 119.7,80.71 119.65,80.67 119.62,80.63 119.25,80.26 119.25,74.3 116.33,71.37 108.33,71.37 107.95,71.75 107.95,75.06 108.2,75.31 112.14,75.31 112.4,75.06 115.57,75.06 116.08,75.56 116.08,84.2 116.33,84.45 122.3,84.45
VCC_3V3_B on TOP: 29.46,63.5 26.29,63.5 26.04,63.25 26.04,59.56 26.8,58.8 29.46,58.8 29.72,59.05 29.72,63.25
VCC_3V3_B on TOP: 29.46,77.47 27.18,77.47 26.92,77.22 26.92,75.82 27.05,75.69 27.56,75.69 27.94,76.07 29.46,76.07 29.59,76.2 29.59,77.34
VCC_3V3_B on BOTTOM: 32.26,84.45 32.26,77.6 32.51,77.34 33.91,77.34 34.04,77.47 34.04,84.45 33.91,84.58 32.38,84.58
VCC_3V3_B on BOTTOM: 26.04,59.56 26.04,63.63 26.16,63.75 27.43,63.75 27.56,63.63 27.56,59.56 27.18,59.18 26.42,59.18
VCC_3V3_B on BOTTOM: 27.69,77.47 26.67,77.47 26.54,77.34 26.54,75.18 26.67,75.06 27.69,75.06 27.81,75.18 27.81,77.34
VCC_3V3_B on POWER: 116.46,97.28 1.65,97.28 1.65,74.68 24.13,74.68 25.02,73.79 25.02,49.02 112.52,49.02 112.52,67.94 119.63,75.06 119.63,83.95 119.13,84.45 116.97,84.45 116.46,84.96
VCC_12V0 on TOP: 120.65,84.84 116.84,84.84 116.46,85.22 116.46,91.95 115.7,92.71 108.84,92.71 107.7,93.85 107.7,95.88 108.46,96.65 119.51,96.65 121.03,95.12 121.03,85.22
VCC_12V0 on TOP: 116.59,17.78 113.92,17.78 113.03,18.67 113.03,31.11 114.17,32.26 120.78,32.26 121.29,31.75 121.29,26.92 118.11,23.75 118.11,21.34 116.97,20.19 116.97,18.16
VCC_12V0 on TOP, BOTTOM: 147.27,41.3 148.79,42.82 148.79,52.1 147.65,53.24 136.35,53.24 135.33,52.22 135.33,42.95 136.98,41.3
VCC_12V0 on BOTTOM: 122.68,84.84 116.84,84.84 116.46,85.22 116.46,91.95 115.7,92.71 108.84,92.71 107.7,93.85 107.7,95.88 108.46,96.65 129.67,96.65 131.19,95.12 131.19,85.85 131.06,85.72 128.91,85.72 128.91,88.14 128.78,88.27 123.32,88.27 123.19,88.14 123.19,85.34
VCC_12V0 on BOTTOM: 126.37,32.26 114.17,32.26 113.41,31.5 113.41,17.65 119.89,17.65 120.14,17.91 120.14,21.08 120.4,21.34 125.09,21.34 125.6,20.83 125.6,18.92 126.11,18.41 127.38,18.41 127.89,18.92 127.89,30.73
VCC_12V0 on POWER: 116.84,97.28 116.84,85.47 117.48,84.84 119.25,84.84 120.02,84.07 120.02,74.93 112.9,67.82 112.9,19.81 114.05,18.67 114.94,18.67 116.59,17.02 116.59,2.03 166.5,2.03 166.5,97.28
VCC_12V_AUX on TOP, BOTTOM: 157.43,52.86 157.43,72.16 156.54,73.05 151.71,73.05 151.08,72.42 151.08,52.86 151.71,52.22 156.79,52.22
VCC_12V_AUX on POWER: 156.54,73.05 151.71,73.05 151.08,72.42 151.08,52.86 151.71,52.22 156.79,52.22 157.43,52.86 157.43,72.16
(no net) on TOP: 119.02,17.27 119.14,17.14 119.14,13.72 119.02,13.59 116.48,13.59 115.97,13.08 115.97,3.83 115.7,3.56 112.27,3.56 112.01,3.81 112.01,7.62 112.27,7.87 112.29,7.87 112.79,8.38 112.79,17.02 113.05,17.27
(no net) on TOP: 128.02,80.52 119.76,80.52 119.51,80.26 119.51,77.47 119.76,77.22 121.54,77.22 121.67,77.34 121.67,78.23 122.05,78.61 128.65,78.61 128.91,78.36 128.91,76.83 129.41,76.33 131.06,76.33 131.44,76.71 131.44,79.5 131.19,79.76 128.78,79.76
(no net) on TOP: 129.03,76.07 121.41,76.07 120.65,75.31 120.65,73.15 121.03,72.77 132.46,72.77 133.98,74.3 133.98,87.88 133.48,88.39 122.05,88.39 121.41,87.76 121.41,85.72 121.67,85.47 122.43,85.47 122.56,85.6 122.56,87.25 131.44,87.25 131.83,86.87 131.83,76.58 131.19,75.95 129.16,75.95
(no net) on TOP: 119.89,14.1 119.89,16.38 119.91,16.38 120.8,17.27 125.37,17.27 126.26,18.16 127.64,18.16 128.02,17.78 128.02,12.95 127.89,12.83 126.13,12.83 125.24,13.72 120.27,13.72
(no net) on TOP: 123.17,81.28 123.17,83.57 123.19,83.57 124.08,84.45 128.65,84.45 129.54,85.34 130.92,85.34 131.3,84.96 131.3,80.14 131.17,80.01 129.41,80.01 128.52,80.9 123.55,80.9
(no net) on TOP: 125.75,8.89 118.13,8.89 117.37,8.13 117.37,5.97 117.75,5.59 129.18,5.59 130.7,7.11 130.7,20.7 130.19,21.21 118.67,21.21 118.06,20.6 118.06,17.83 118.24,17.65 119.13,17.65 119.27,17.8 119.27,19.75 119.58,20.07 128.14,20.07 128.54,19.67 128.54,9.4 127.91,8.76 125.88,8.76
(no net) on TOP: 124.73,13.33 116.48,13.33 116.22,13.08 116.22,10.29 116.48,10.03 118.26,10.03 118.38,10.16 118.38,11.05 118.76,11.43 125.37,11.43 125.62,11.18 125.62,9.65 126.13,9.14 127.78,9.14 128.16,9.53 128.16,12.32 127.91,12.57 125.49,12.57
(no net) on TOP, BOTTOM: 122.3,84.45 122.43,84.33 122.43,80.9 122.3,80.77 119.76,80.77 119.25,80.26 119.25,74.3 116.33,71.37 108.33,71.37 107.95,71.75 107.95,75.06 108.2,75.31 112.14,75.31 112.4,75.06 115.57,75.06 116.08,75.56 116.08,84.2 116.33,84.45
(no net) on BOTTOM: 124.48,5.59 117.75,5.59 117.37,5.97 117.37,8.13 117.49,8.26 122.95,8.26 123.97,9.27 123.97,11.05 124.73,11.05 124.73,5.84
(no net) on BOTTOM: 119.02,17.27 119.14,17.14 119.14,13.72 119.02,13.59 116.48,13.59 115.97,13.08 115.97,7.11 115.96,7.1 115.96,3.82 115.7,3.56 112.27,3.56 112.01,3.81 112.01,7.62 112.14,7.75 112.16,7.75 112.79,8.38 112.79,17.02 113.05,17.27
(no net) on BOTTOM: 127.76,72.77 121.03,72.77 120.65,73.15 120.65,75.31 120.78,75.44 126.24,75.44 127.25,76.45 127.25,78.23 128.02,78.23 128.02,73.02
(no net) on BOTTOM: 123.17,81.28 123.17,83.57 123.19,83.57 124.08,84.45 128.65,84.45 129.54,85.34 130.92,85.34 131.3,84.96 131.3,80.14 131.17,80.01 129.41,80.01 128.65,80.77 123.68,80.77
(no net) on BOTTOM: 119.89,14.1 119.89,16.38 119.91,16.38 120.8,17.27 125.37,17.27 126.26,18.16 127.64,18.16 128.02,17.78 128.02,12.95 127.89,12.83 126.13,12.83 125.37,13.59 120.4,13.59
(no net) on BOTTOM: 124.73,13.33 116.48,13.33 116.22,13.08 116.22,10.29 116.48,10.03 118.26,10.03 118.38,10.16 118.38,11.05 118.76,11.43 125.37,11.43 125.62,11.18 125.62,9.65 126.13,9.14 127.4,9.14 127.91,9.65 127.91,12.45 127.78,12.57 125.49,12.57
(no net) on BOTTOM: 128.02,80.52 119.76,80.52 119.51,80.26 119.51,77.47 119.76,77.22 121.54,77.22 121.67,77.34 121.67,78.23 122.05,78.61 128.65,78.61 128.91,78.36 128.91,76.83 129.41,76.33 130.68,76.33 131.19,76.83 131.19,79.63 131.06,79.76 128.78,79.76
(no net) on GROUND: 123.17,81.28 123.17,84.03 123.67,84.53 129.11,84.53 129.26,84.38 129.26,81.18 128.98,80.9 123.55,80.9
(no net) on GROUND: 119.79,14.2 119.79,16.84 120.22,17.27 125.73,17.27 126.06,16.94 126.06,14.12 125.65,13.72 120.27,13.72
P_12V_ON on TOP, BOTTOM: 138.76,38.38 142.06,38.38 142.32,38.13 142.32,35.2 142.44,35.08 143.08,35.08 143.59,34.57 143.59,33.68 142.82,32.92 140.79,32.92 140.03,33.68 139.14,33.68 138.38,34.44 138.38,38
N16765603 on TOP, BOTTOM, POWER: 158.95,29.49 159.46,30 159.46,41.3 158.95,41.81 152.73,41.81 151.97,41.05 151.97,39.78 151.21,39.01 144.6,39.01 143.97,38.38 143.97,30.38 144.86,29.49
N19467364 on TOP (solid shape): 128.02,17.78 128.02,12.95 126,12.95 125.24,13.72 124.89,13.72 124.89,13.72 120.27,13.72 119.89,14.1 119.89,16.36 120.8,17.27 125.37,17.27 126.26,18.16 127.64,18.16
N19467364 on BOTTOM (solid shape): 128.02,17.78 128.02,12.95 127.89,12.83 126.13,12.83 125.37,13.59 120.4,13.59 119.89,14.1 119.89,16.36 120.8,17.27 125.37,17.27 126.26,18.16 127.64,18.16
N19467364 on GROUND (solid shape): 126.06,16.94 126.06,14.12 125.65,13.72 120.27,13.72 119.79,14.2 119.79,16.84 120.22,17.27 125.73,17.27
N19467364 on POWER: 119.84,14.15 119.84,16.41 120.7,17.27 125.73,17.27 126.06,16.94 126.06,14.12 125.65,13.72 120.27,13.72
N19472498 on TOP (solid shape): 131.3,84.96 131.3,80.14 129.29,80.14 128.52,80.9 128.17,80.9 128.17,80.9 123.55,80.9 123.17,81.28 123.17,83.55 124.08,84.45 128.65,84.45 129.54,85.34 130.92,85.34
N19472498 on BOTTOM (solid shape): 131.3,84.96 131.3,80.14 131.17,80.01 129.41,80.01 128.65,80.77 123.68,80.77 123.17,81.28 123.17,83.55 124.08,84.45 128.65,84.45 129.54,85.34 130.92,85.34
N19472498 on GROUND (solid shape): 129.26,84.38 129.26,81.18 128.98,80.9 123.55,80.9 123.17,81.28 123.17,84.03 123.67,84.53 129.11,84.53
N19472498 on POWER: 123.17,81.28 123.17,84.03 123.67,84.53 129.11,84.53 129.26,84.38 129.26,81.18 128.98,80.9 123.55,80.9
N19510410 on TOP: 158.57,28.73 158.95,28.35 158.95,24.92 158.45,24.41 154,24.41 153.49,24.92 153.49,28.73
N19528011 on TOP, BOTTOM, POWER: 152.73,46.76 152.73,43.21 153.62,42.32 157.18,42.32 157.94,43.08 157.94,47.02 157.43,47.52 153.49,47.52

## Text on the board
BOTTOM: PCB_501-1-00592_B1
Ref Des/Assembly Bottom: ASSEMBLY BOTTOM
User.Comments: CR_3V3_2 | DESIGNED FOR: | DELU_ADPT | LAYER:
Ref Des/Assembly Top: ASSEMBLY TOP
Ref Des/Silkscreen Top: PCB_501-1-00592_B1
Board Geometry/Design Outline: BOARD ORIGIN (0,0)
DIMENSION: B1 | 21-JUN-17 | ASSEMBLY RELEASE | SHEMATIC UPDATE | JESS
FAB_NOTES: LAYER STACKUP DETAILS | SOLDER MASK | 0.8 mil | L1 Cu, 0.7 mil + plating | 3.76 mil, PREPEG | 44.88 mil, CORE | L2 Cu, 1.4 mil | L3 Cu, 1.4 mil | L4 Cu, 0.7 mil + plating | LAYER NAME | BOTTOM | TOP | 6 MILS | 50 OHMS | IMPEDANCE TABLE | WIDTH | IMPEDANCE REQUIREMENT | 4.5 MILS | 100 OHMS | 7.5 MILS | SPACING | 1.6 +\- 0.16MM | 18) | 20) | 12) | 13) | 14) | 15) | 19) | 10) | 16) | 17) | 11) | 1 | 2 | 3) | 4) | 5) | 6) | 8) | 9) | 7) | IPC_ | ART_PARAM_ | SSB_ | SST_ | SMB_ | SMT_ | FAB_ | DRL_ | NC_TOOLS_ | ART_APER_ | PMT_ | TOP_ | NC_PARAM_ | RFQ_ | PMB_ | BOTTOM_501-1-00592_B1.ART   - | L2_GND_ | L3_PWR_ | NOTES: UNLESS OTHERWISE SPECIFIED | MATERIAL | FINISH | MATERIAL: UL RECOGNIZED COMPONENT ZPMV2, 94V-1 MINIMUM. | 501-1-00592_B1 | 501-1-00592_B1.ZIP CONSISTS OF | APPLY LPI SOLDER MASK TO INDICATED SIDES OVER BARE COPPER. | LAYER TO LAYER REGISTRATION SHALL BE WITHIN 0.08 FIM. | SILKSCREEN SHOULD BE NON-CONDUCTIVE EPOXY INK. | BOARD THICHNESS WHICH EVER MENTIONED IS WITH PLATING. | MARK WITH VENDOR LOGO AND DATE CODE.SHALL BE ANYWHERE ON SILKSCREEN | FABRICATE TO THE REQUIREMENTS OF IPC-A-600. | ETCH PER GERBER FILES TOP_501-1-00592_B1.ART THRU BOTTOM_501-1-00592_B1.ART | LABELING SHALL NOT BE PLACED OVER EXPOSED COPPER. | THERE ARE IMPEDANCE CONTROLED SIGNALS RUNNING INSIDE BOARD. | VENDOR SHOULD NOT MODIFY ARTWORK EXCEPT FOR PROCESS CONTROL. | ALL PCB MATERIAL SHOULD BE ROHS COMPLIANT AND LEAD FREE. | HANDLE, PACKAGE, AND SHIP CAREFULLY THAT TO ENSURE NO DAMAGE. | 4NOS OF FIDUCIAL ON TOP SIDE AND 4NOS OF 3.2MM TOOLING HOLES ARE REQUIRED ON BREAKAWAY STRIP. | FAB VENDOR SHOULD PROVIDE 5MM BREAKAWAY STRIP ON TWO (OPPOSITE) SIDES, ALSO | ALL SHARP CORNERS (EXTERNALS) TO BE CHAMFERED BY 1X45 DEGREE | UNLESS OTHERWISE SPECIFIED . | BOARD SHOULD BE 100% ELECTRICALLY TESTED FOR OPEN AND SHORT CIRCUIT. | ALL HOLE DIAMETER TO BE  +/-0.075mm  UNLESS OTHERWISE SPECIFIED. | ALL HOLE DIAMETERS  ARE FINISHED SIZE. | BOW AND TWIST SHAL NOT EXCEED 0.75% OR AS PER  IPC APPLICABLE CLAUSE. | MANDATORY BAKE REQUIREMENT MUST BE MENTIONED IN THE PACKING BOX. | SEE DETAIL A. | GOLD PLATING 0.076-0.2 MICRONS THICK | ENIG (ELECTROLESS NICKEL IMMERSION GOLD) AFTER COPPER PLATING, | PLATE ELECTROLESS NICKEL 1-4 MICRONS THICK FOLLOWED BY AN IMMERSION | .ART -       LAYER 01 (TOP SIDE) | .ART -       SILKSCREEN BOTTOM | .ART -       SILKSCREEN TOP | .ART -       LAYER 02 (INNER LAYER 1) | .ART -       SOLDERMASK BOTTOM | .ART -       SOLDERMASK TOP | .ART -       PASTEMASK TOP | .PDF -       FABRICATION DRAWING | .ART -       PASTEMASK BOTTOM | .IPC -      IPC 356 NETLIST | .ART -       LAYER 03 (INNER PLANE 2) | .XLS -      RFQ DOCUMENT | .DRL -      NC DRILL | .TXT -  NC TOOLS REPORT | .TXT -  NC DRILL PARAMETERS | LAYER 04 (BOTTOM SIDE) | .TXT - ART PARAMETER | .TXT - ART APERTURE | (0,0)
FAB_DRAWING: BPCB,4L,168X98.4mm,DELU_ADPT, | M.2 Adaptor Card | B1 | A1 | 21-JUN-17 | 27-FEB-17 | SHEMATIC UPDATE | FAB RELEASE | 501-1-00592 | NANDHA | JESS
User.6: FAB DRAWING
User.7: EXAMPLE FEATURE: | AREA FREE OF SOLDERMASK | TOP SOLDER
User.8: EXAMPLE FEATURE: | AREA FREE OF SOLDERMASK | BOTTOM SOLDER
User.9: TOP PASTE | FIDUCIAL'S  WILL NOT BE THRU OPEN IT SHOULD BE HALFETCH
User.10: BOTTOM PASTE | FIDUCIAL'S  WILL NOT BE THRU OPEN IT SHOULD BE HALFETCH
User.11: TOP SILK
User.12: BOTTOM SILK
User.13: TOP
User.14: GND
User.15: PWR
User.16: BOTTOM
User.17: FIGURE | FINISHED_SIZE | 8.0 | 12.0 | 74.0 | 126.0 | 128.0 | 146.0 | 43.0 | 44.0 | 63.0 | 121.0 | DRILL CHART: TOP to BOTTOM | ALL UNITS ARE IN MILS | PLATED | NON-PLATED | QTY | 236 | 442 | 6 | 4 | 2 | 10
User.18: CONNECTOR EDGE
User.19: UPDATED MANUALLY | NEEDS TO BE | B | A | D | C | ASY 501-1-00592_A1.ZIP CONSISTS OF FOLLOWING ASSEMBLY DATA | 501-1-00592_A1_PMT .ART -  TOP PASTE (TOP PASTE) | 501-1-00592_A1_PNP .TXT -  PICK AND PLACE DATA | 501-1-00592_A1_PMB .ART -  BOTTOM PASTE (BOTTOM PASTE) | 1 | 2 | BOARD ORIGIN (0,0) | 3 | PCB SECONDARY SIDE | MAXIMUM HEIGHT 11.5 MM | PCB PRIMARY SIDE | MAXIMUM HEIGHT10.5 MM | 4 | 5 | 6 | NOTES:          UNLESS OTHERWISE SPECIFIED. | CAUTION :       COMPONENTS ARE SUBJECT TO DAMAGE BY STATIC ELECTRICITY. | 7) STICK TO THE BACKING REQUIREMENT AS PER CLASS RECOMMENEDATION. | 8) "FIDUCIAL'S  WILL NOT BE THRU OPEN, IT SHOULD BE HALFETCH". | 2) LABELS SHALL NOT TO BE PLACED OVER EXPOSED COPPER AND METAL. | 3) SOLDER PASTE TOOLING SHOULD BE MADE USING PMT_501-1-00592_A1.ART FOR PRIMARY SIDE. | 5) APERTURES MAY BE MODIFIED TO BEST FIT VVDN REQUIREMENT. | 6) ASSEMBLY SHALL BE ELCECTRICALLY TESTED. | 1) SOLDER AND ASSEMBLE AS PER INDUSTRY WORKMANSHIP STANDARDS. | 4) SOLDER PASTE TOOLING SHOULD BE MADE USING PMB_501-1-00592_A1.ART FOR SECONDARY SIDE. | REV | A1 | 27-FEB-17 | DATE | 7 | ASSEMBLY RELEASE | REVISION NOTES | TITLE: | APCB,DS,DELU_ADPT,M.2 Adaptor Card | PCBA ASSEMBLY DRAWING | ASY NUMBER: | VVDN TECHNOLOGIES PVT.LTD. | 701-1-00687 | 8 | PCB_DESIGNER | NANDHA
User.21: UPDATED MANUALLY | NEEDS TO BE | B | A | D | C | ASY 501-1-00592_B1.ZIP CONSISTS OF FOLLOWING ASSEMBLY DATA | 501-1-00592_B1_PMT .ART -  TOP PASTE (TOP PASTE) | 501-1-00592_B1_PNP .TXT -  PICK AND PLACE DATA | 501-1-00592_B1_PMB .ART -  BOTTOM PASTE (BOTTOM PASTE) | 1 | 2 | BOARD ORIGIN (0,0) | 3 | PCB SECONDARY SIDE | MAXIMUM HEIGHT 11.5 MM | PCB PRIMARY SIDE | MAXIMUM HEIGHT10.5 MM | 4 | 5 | 6 | NOTES:          UNLESS OTHERWISE SPECIFIED. | CAUTION :       COMPONENTS ARE SUBJECT TO DAMAGE BY STATIC ELECTRICITY. | 7) STICK TO THE BACKING REQUIREMENT AS PER CLASS RECOMMENEDATION. | 8) "FIDUCIAL'S  WILL NOT BE THRU OPEN, IT SHOULD BE HALFETCH". | 2) LABELS SHALL NOT TO BE PLACED OVER EXPOSED COPPER AND METAL. | 3) SOLDER PASTE TOOLING SHOULD BE MADE USING PMT_501-1-00592_B1.ART FOR PRIMARY SIDE. | 5) APERTURES MAY BE MODIFIED TO BEST FIT VVDN REQUIREMENT. | 6) ASSEMBLY SHALL BE ELCECTRICALLY TESTED. | 1) SOLDER AND ASSEMBLE AS PER INDUSTRY WORKMANSHIP STANDARDS. | 4) SOLDER PASTE TOOLING SHOULD BE MADE USING PMB_501-1-00592_B1.ART FOR SECONDARY SIDE. | REV | B1 | A1 | 27-FEB-17 | 21-JUN-17 | DATE | 7 | ASSEMBLY RELEASE | SHEMATIC UPDATE | REVISION NOTES | TITLE: | APCB,DS,DELU_ADPT,M.2 Adaptor Card | PCBA ASSEMBLY DRAWING | ASY NUMBER: | VVDN TECHNOLOGIES PVT.LTD. | 701-1-00687 | 8 | PCB_DESIGNER | NANDHA | JESS
